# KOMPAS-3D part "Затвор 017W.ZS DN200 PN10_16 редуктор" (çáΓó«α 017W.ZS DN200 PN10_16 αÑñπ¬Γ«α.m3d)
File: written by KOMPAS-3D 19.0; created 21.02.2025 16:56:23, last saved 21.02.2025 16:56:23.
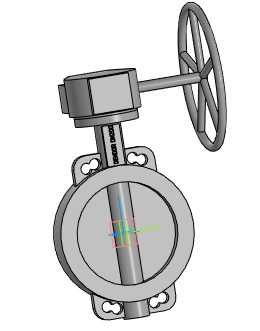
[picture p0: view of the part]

Document properties: Автор: Евгений; Полное имя файла: Затвор 017W.ZS DN200 PN10_16 редуктор.a3d

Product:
- Part/product: Затвор 017W.ZS DN200 PN10_16 редуктор
    Масса: 36.5641

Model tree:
1. Операция без истории:1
